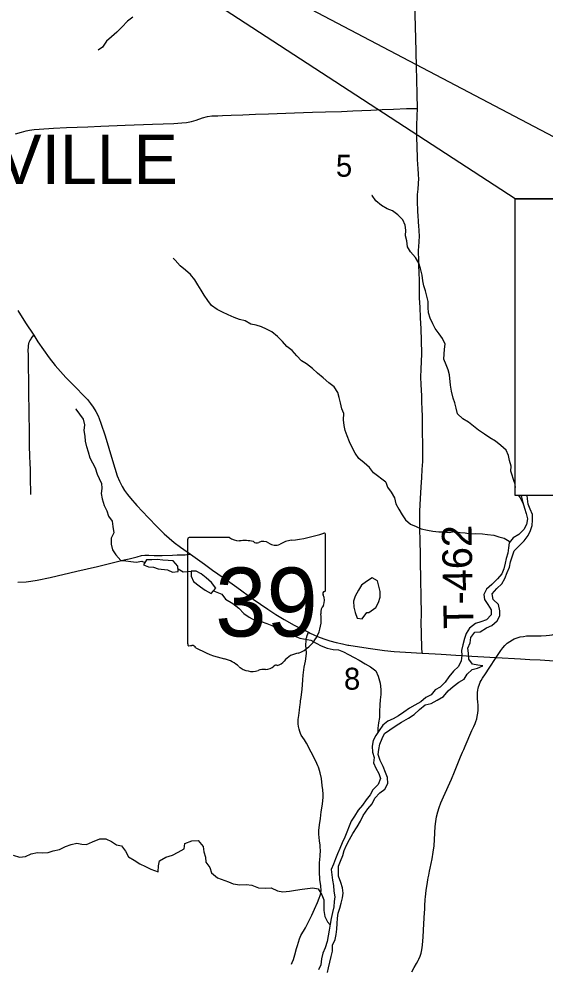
# Model space of a CAD drawing. Extents: x -7.5 to 53.5, y 0 to 22.
# Drawn here: x 5.577 to 6.583, y 15.27 to 17.086 of the extents above; entities that cross this region are included whole.
import ezdxf

# ---------------------------------------------------------------- set-up
doc = ezdxf.new("R2010")
doc.units = 0
for name, color, linetype in [('GM_X_Corporation_Text', 7, 'Continuous'), ('GM_X_Major_River', 7, 'Continuous'), ('GM_X_Minor_Lake', 7, 'Continuous'), ('GM_X_Minor_River', 7, 'Continuous'), ('GM_X_Section_Text', 7, 'Continuous'), ('GM_X_State_Location', 7, 'Continuous'), ('GM_X_State_Route', 7, 'Continuous'), ('GM_X_State_Shield', 7, 'Continuous'), ('GM_X_Township_Road', 7, 'Continuous'), ('GM_X_Township_Road_Text', 7, 'Continuous'), ('SH_Text', 7, 'Continuous')]:
    doc.layers.add(name, color=color, linetype=linetype)

msp = doc.modelspace()

# ---------------------------------------------------------------- linework, layer by layer
at = {"layer": 'GM_X_Major_River'}
for points in [[(6.5379, 16.1744), (6.5382, 16.1712), (6.5406, 16.161), (6.5437, 16.1504), (6.5472, 16.1398), (6.5496, 16.1299), (6.5478, 16.1189), (6.5429, 16.1094), (6.5332, 16.0998), (6.5226, 16.0933), (6.5148, 16.0837), (6.5137, 16.0742), (6.5119, 16.064), (6.509, 16.0541), (6.5072, 16.0446), (6.5046, 16.0343), (6.5009, 16.0248), (6.4923, 16.0149), (6.4818, 16.0038), (6.4716, 15.995), (6.466, 15.9851), (6.4672, 15.9756), (6.4741, 15.9658), (6.4803, 15.9556), (6.48, 15.9461), (6.4714, 15.9362), (6.4608, 15.9327), (6.4502, 15.9296), (6.4386, 15.9207), (6.4322, 15.9104), (6.4293, 15.9009), (6.426, 15.8884), (6.4238, 15.8777), (6.4243, 15.8683), (6.4228, 15.858), (6.418, 15.847), (6.4082, 15.8385), (6.3996, 15.8275), (6.3921, 15.8172), (6.3828, 15.8076), (6.3729, 15.8026), (6.3655, 15.793), (6.3556, 15.788), (6.3459, 15.7796), (6.3342, 15.773), (6.3244, 15.7673), (6.3135, 15.76), (6.3033, 15.7527), (6.2931, 15.7473), (6.2826, 15.7423), (6.2728, 15.735), (6.266, 15.7247), (6.2597, 15.7151), (6.2548, 15.7056), (6.2527, 15.695), (6.2532, 15.6832), (6.2563, 15.673), (6.2552, 15.6631), (6.2599, 15.6529), (6.2656, 15.6427), (6.2688, 15.6329), (6.2639, 15.6211), (6.2542, 15.6111), (6.2486, 15.6016), (6.2411, 15.5921), (6.234, 15.5821), (6.2261, 15.5726), (6.219, 15.5608), (6.2123, 15.5512), (6.209, 15.5417), (6.2045, 15.5303), (6.2004, 15.5204), (6.1956, 15.5101), (6.1908, 15.4991), (6.1867, 15.4888), (6.1826, 15.4789), (6.1789, 15.469), (6.1745, 15.4591), (6.1753, 15.4485), (6.1766, 15.4386), (6.1789, 15.4284), (6.1794, 15.4174), (6.1814, 15.4068), (6.18, 15.3973), (6.1793, 15.3871), (6.1767, 15.3768), (6.1742, 15.365), (6.1724, 15.354), (6.1702, 15.343), (6.1688, 15.332), (6.1666, 15.3213), (6.163, 15.3092), (6.1585, 15.2985), (6.156, 15.2879), (6.1545, 15.2765), (6.1501, 15.2666)], [(6.1676, 15.2614), (6.1694, 15.2709), (6.1716, 15.2815), (6.1745, 15.2926), (6.1767, 15.3024), (6.1766, 15.3138), (6.1818, 15.3249), (6.1836, 15.3347), (6.185, 15.3446), (6.186, 15.3556), (6.1863, 15.3655), (6.1874, 15.375), (6.1911, 15.3849), (6.1936, 15.3944), (6.1962, 15.4043), (6.1973, 15.4138), (6.196, 15.424), (6.1925, 15.4338), (6.1886, 15.4463), (6.1884, 15.4653), (6.1922, 15.4748), (6.1966, 15.4855), (6.1992, 15.495), (6.2036, 15.5053), (6.2096, 15.5159), (6.2159, 15.5274), (6.2238, 15.5403), (6.2301, 15.551), (6.2357, 15.5624), (6.2447, 15.5746), (6.2525, 15.5846), (6.2581, 15.5952), (6.2671, 15.6052), (6.2769, 15.6125), (6.2829, 15.6235), (6.282, 15.6345), (6.2781, 15.6444), (6.2735, 15.6557), (6.2677, 15.6674), (6.2642, 15.6788), (6.2652, 15.6886), (6.2674, 15.6985), (6.2719, 15.7092), (6.2763, 15.7187), (6.2865, 15.726), (6.2985, 15.7341), (6.3087, 15.741), (6.3223, 15.7483), (6.3332, 15.7556), (6.3434, 15.7652), (6.3543, 15.7736), (6.3656, 15.7763), (6.3769, 15.7829), (6.3894, 15.7898), (6.398, 15.8009), (6.4077, 15.8089), (6.4183, 15.817), (6.4288, 15.8232), (6.4341, 15.8327), (6.4442, 15.8415), (6.4544, 15.8439), (6.4646, 15.8485), (6.4547, 15.8499), (6.4445, 15.8514), (6.4376, 15.8615), (6.4371, 15.8725), (6.4359, 15.882), (6.4403, 15.8923), (6.4414, 15.9029), (6.4492, 15.9129), (6.4595, 15.9137), (6.4711, 15.921), (6.4813, 15.9256), (6.4915, 15.9345), (6.4967, 15.944), (6.497, 15.9535), (6.4942, 15.966), (6.4839, 15.9757), (6.4819, 15.9863), (6.4909, 15.9963), (6.5007, 16.0055), (6.5067, 16.0154), (6.5111, 16.0268), (6.5156, 16.0375), (6.5174, 16.0473), (6.521, 16.0588), (6.5244, 16.0683), (6.5338, 16.0778), (6.5435, 16.0874), (6.551, 16.0977), (6.5555, 16.1076), (6.5588, 16.1171), (6.5591, 16.1274), (6.559, 16.138), (6.5551, 16.1482), (6.5508, 16.158), (6.5496, 16.1683), (6.5491, 16.1744)]]:
    msp.add_lwpolyline(points, dxfattribs=at)
at = {"layer": 'GM_X_Minor_Lake'}
for points in [[(5.8724, 16.0492), (5.8626, 16.0502), (5.8527, 16.0505), (5.8413, 16.052), (5.8311, 16.0511), (5.8209, 16.051), (5.8153, 16.0415), (5.8248, 16.0378), (5.8343, 16.0375), (5.8438, 16.0342)], [(5.8438, 16.0342), (5.8616, 16.0324), (5.8711, 16.0276), (5.8817, 16.0288), (5.8812, 16.0394), (5.8724, 16.0492)], [(5.9352, 16.0167), (5.9257, 16.0242), (5.9162, 16.0295), (5.9067, 16.0298), (5.9064, 16.0203), (5.9114, 16.0101), (5.9221, 16.0014), (5.9244, 15.9995)], [(5.9244, 15.9995), (5.9336, 15.9932), (5.9446, 15.9868), (5.9536, 15.9968), (5.9452, 16.0081), (5.9352, 16.0167)], [(6.2631, 16.0111), (6.2528, 16.0171), (6.2419, 16.0098), (6.2321, 16.0025), (6.2265, 15.993), (6.2205, 15.9815), (6.2168, 15.972), (6.2177, 15.961), (6.22, 15.9508), (6.2243, 15.9398), (6.2338, 15.9384), (6.2424, 15.9506), (6.2466, 15.9502)], [(6.2466, 15.9502), (6.2597, 15.9602), (6.2646, 15.9697), (6.2683, 15.98), (6.2678, 15.9906), (6.2654, 16.0012), (6.2631, 16.0111)]]:
    msp.add_lwpolyline(points, dxfattribs=at)
at = {"layer": 'GM_X_Minor_River'}
for points in [[(5.7948, 17.0893), (5.7846, 17.0818), (5.7742, 17.0705), (5.7647, 17.0607), (5.7544, 17.0521), (5.7448, 17.0435), (5.7368, 17.0322), (5.7291, 17.0262)], [(6.5251, 16.1992), (6.5181, 16.2208), (6.5185, 16.2306), (6.5156, 16.2416), (6.5134, 16.2511), (6.5089, 16.261), (6.4987, 16.2698), (6.4886, 16.2783), (6.4776, 16.2848), (6.4675, 16.2917), (6.4562, 16.2991), (6.4366, 16.3144), (6.4264, 16.3209), (6.4159, 16.3305), (6.4133, 16.3415), (6.4111, 16.3514), (6.4078, 16.3609), (6.4041, 16.3739), (6.4027, 16.3852), (6.4006, 16.405), (6.398, 16.4149), (6.3939, 16.4244), (6.3898, 16.435), (6.3903, 16.4445), (6.3911, 16.4544), (6.3923, 16.4642), (6.3875, 16.4745), (6.3807, 16.484), (6.3729, 16.4936), (6.3688, 16.5031), (6.3636, 16.5138), (6.3602, 16.5237), (6.3596, 16.5339), (6.3596, 16.5453), (6.3571, 16.5555), (6.3549, 16.5658), (6.3516, 16.5753), (6.3497, 16.5852), (6.3483, 16.5962), (6.3454, 16.6084), (6.3421, 16.619), (6.3353, 16.6297), (6.3259, 16.6404), (6.3203, 16.6503), (6.3189, 16.6617), (6.3163, 16.6712), (6.3172, 16.6822), (6.3161, 16.6917), (6.3113, 16.7016), (6.3019, 16.7111), (6.2913, 16.7192), (6.2811, 16.7227), (6.2706, 16.7293), (6.26, 16.7381), (6.2529, 16.7484), (6.2518, 16.7484)], [(6.2791, 16.2002), (6.255, 16.2175), (6.2475, 16.2281), (6.2373, 16.2366), (6.2275, 16.245), (6.2204, 16.2553), (6.2144, 16.266), (6.2096, 16.277), (6.2048, 16.2884), (6.2011, 16.2987), (6.1993, 16.3082), (6.1982, 16.3192), (6.1983, 16.331), (6.195, 16.3405), (6.1924, 16.3519), (6.1898, 16.3618), (6.1869, 16.3713), (6.1802, 16.382), (6.17, 16.39), (6.1591, 16.3992), (6.1485, 16.4084), (6.1384, 16.4172), (6.1271, 16.4261), (6.1173, 16.4318), (6.1086, 16.4414), (6.1, 16.4517), (6.0898, 16.4594), (6.0812, 16.4689), (6.0714, 16.4789), (6.0609, 16.4877), (6.0507, 16.4927), (6.0409, 16.4974), (6.0307, 16.5001), (6.0208, 16.5021), (6.0099, 16.5083), (5.9989, 16.511), (5.9891, 16.5149), (5.9774, 16.5203), (5.9668, 16.5253), (5.9566, 16.5304), (5.9457, 16.5381), (5.9386, 16.5476), (5.9314, 16.5579), (5.9258, 16.5674), (5.9195, 16.5773), (5.9135, 16.5873), (5.9056, 16.5972), (5.8958, 16.6052), (5.8853, 16.6141), (5.8763, 16.6244), (5.8721, 16.6286)], [(5.735, 16.1979), (5.7273, 16.2143), (5.7237, 16.2265), (5.7188, 16.236), (5.7136, 16.2459), (5.7106, 16.2573), (5.7069, 16.2672), (5.7044, 16.2782), (5.7037, 16.2881), (5.7023, 16.2987), (5.7035, 16.3097), (5.7009, 16.3207), (5.6867, 16.3398), (5.6863, 16.3402)], [(5.735, 16.1979), (5.7355, 16.188), (5.7348, 16.1782), (5.7365, 16.1683), (5.7404, 16.1551), (5.7454, 16.1453), (5.7485, 16.135), (5.7554, 16.1252), (5.757, 16.115), (5.7586, 16.1029), (5.7538, 16.093), (5.7539, 16.0812), (5.7563, 16.0706), (5.7624, 16.0608), (5.772, 16.0503), (5.7815, 16.0492), (5.7914, 16.0478), (5.8016, 16.0467), (5.8126, 16.0487), (5.8179, 16.046)], [(6.2791, 16.2002), (6.2819, 16.1903), (6.2892, 16.1805), (6.2957, 16.1696), (6.2981, 16.1582), (6.3039, 16.148), (6.31, 16.1374), (6.3166, 16.1276), (6.3261, 16.1197), (6.3368, 16.1153), (6.3467, 16.1108), (6.3588, 16.1082), (6.3687, 16.1064), (6.38, 16.105), (6.3895, 16.1051), (6.3998, 16.1033), (6.4096, 16.1053), (6.421, 16.1034), (6.4305, 16.1028), (6.4403, 16.1013), (6.4509, 16.1018), (6.4634, 16.1011), (6.4733, 16.0997), (6.4854, 16.0983), (6.4949, 16.0953), (6.5052, 16.0928), (6.5147, 16.0868), (6.5162, 16.0855)], [(6.5251, 16.1992), (6.5259, 16.1897), (6.5259, 16.1896)], [(6.5323, 16.1744), (6.5356, 16.17), (6.5409, 16.1596)], [(5.8815, 16.034), (5.8916, 16.0285), (5.9067, 16.0298)], [(5.9494, 15.9921), (5.9655, 15.9859), (5.9724, 15.976), (5.9861, 15.9678), (5.9975, 15.9588), (6.0071, 15.9486), (6.0174, 15.9415), (6.0288, 15.9352), (6.0406, 15.933), (6.0512, 15.9297), (6.0611, 15.9256), (6.0718, 15.9207), (6.0836, 15.9166), (6.0935, 15.9095), (6.1049, 15.9054), (6.1144, 15.9017), (6.1356, 15.8974), (6.1455, 15.8917), (6.1554, 15.8865), (6.1665, 15.8821), (6.1782, 15.8799), (6.1881, 15.8792), (6.198, 15.8755), (6.2075, 15.8699), (6.2185, 15.8647), (6.2281, 15.8594), (6.2395, 15.8523), (6.2498, 15.8467), (6.2597, 15.8392), (6.2643, 15.829), (6.2682, 15.8154), (6.2691, 15.8032), (6.2696, 15.7938), (6.2682, 15.7835), (6.2671, 15.7736), (6.2668, 15.7611), (6.2666, 15.7497), (6.2648, 15.7395), (6.2633, 15.7292), (6.2634, 15.7207)], [(5.5665, 15.4863), (5.5782, 15.4822), (5.5896, 15.4838), (5.6009, 15.4889), (5.6126, 15.4912), (5.6233, 15.4909), (5.6331, 15.4914), (5.6429, 15.4945), (5.6546, 15.4973), (5.6663, 15.5031), (5.6769, 15.5069), (5.6879, 15.5089), (5.6974, 15.5071), (5.7068, 15.5068), (5.7178, 15.5118), (5.7318, 15.5173), (5.7435, 15.5177), (5.7545, 15.5125), (5.7641, 15.5062), (5.7736, 15.5043), (5.7809, 15.4938), (5.787, 15.4828), (5.7977, 15.4768), (5.8087, 15.4697), (5.8194, 15.4645), (5.8293, 15.4593), (5.8434, 15.4541), (5.8444, 15.4655), (5.8462, 15.4754), (5.8579, 15.4823), (5.8707, 15.4862), (5.8817, 15.492), (5.8933, 15.4985), (5.8948, 15.5084), (5.9076, 15.5134), (5.9201, 15.5143), (5.9293, 15.5026), (5.9309, 15.4927), (5.934, 15.4822), (5.9349, 15.4727), (5.9426, 15.4625), (5.9457, 15.4527), (5.9571, 15.4429), (5.9777, 15.4355), (5.9872, 15.4314), (5.9997, 15.4292), (6.0118, 15.4304), (6.0228, 15.429), (6.0354, 15.4238), (6.0479, 15.4228)], [(6.0479, 15.4228), (6.0596, 15.4236), (6.0714, 15.4177), (6.082, 15.4162), (6.0945, 15.4175), (6.1063, 15.4195), (6.1187, 15.4211), (6.129, 15.4223), (6.1392, 15.4239), (6.1494, 15.4221), (6.1567, 15.4104), (6.1606, 15.4006), (6.1603, 15.3907), (6.16, 15.3801), (6.1624, 15.3691), (6.1674, 15.3589), (6.1721, 15.3526)]]:
    msp.add_lwpolyline(points, dxfattribs=at)
at = {"layer": 'GM_X_State_Route'}
for points in [[(5.575, 16.5284), (5.59, 16.5048), (5.6055, 16.4809)], [(5.6055, 16.4809), (5.6137, 16.4684), (5.6241, 16.453), (5.6351, 16.4379), (5.6466, 16.4233), (5.6567, 16.4114), (5.6672, 16.4), (5.6846, 16.3823), (5.702, 16.3647), (5.7083, 16.3578), (5.7141, 16.3506), (5.7194, 16.3431), (5.7242, 16.3352), (5.7285, 16.327), (5.731, 16.3214), (5.7342, 16.3127), (5.7423, 16.2886), (5.7561, 16.2414), (5.7605, 16.2267), (5.7654, 16.2121), (5.7695, 16.2021), (5.7748, 16.1915), (5.7792, 16.1838), (5.7847, 16.1761), (5.7907, 16.169), (5.803, 16.1552), (5.8243, 16.132), (5.8413, 16.1142), (5.8552, 16.101), (5.8644, 16.0926), (5.874, 16.0847), (5.8864, 16.0753), (5.9052, 16.0619)], [(5.9052, 16.0619), (5.9318, 16.043), (5.9477, 16.0317), (5.9679, 16.0174), (5.9807, 16.0083), (5.9939, 15.9988), (6.0252, 15.9762), (6.0532, 15.9567), (6.0688, 15.9465), (6.0847, 15.9369), (6.1037, 15.9263), (6.1175, 15.9192), (6.1309, 15.9126)], [(6.1309, 15.9126), (6.1343, 15.911), (6.1482, 15.9048), (6.1602, 15.9003), (6.172, 15.8964), (6.184, 15.893), (6.1962, 15.8903), (6.2065, 15.8883)], [(6.2065, 15.8883), (6.2084, 15.888), (6.2453, 15.8824), (6.2761, 15.8781), (6.2947, 15.8761), (6.3164, 15.8745), (6.3481, 15.8725)], [(6.3481, 15.8725), (6.3496, 15.8724), (6.3846, 15.8706), (6.4125, 15.8689), (6.4435, 15.867), (6.4776, 15.865), (6.4899, 15.8644)], [(6.4899, 15.8644), (6.5363, 15.8619), (6.5545, 15.8608)], [(6.5545, 15.8608), (6.5737, 15.8597), (6.6009, 15.8583)]]:
    msp.add_lwpolyline(points, dxfattribs=at)
at = {"layer": 'GM_X_State_Shield'}
for p, q in [((5.8999, 16.0906), (5.8999, 15.8905)), ((5.9798, 16.094), (5.9025, 16.094)), ((6.1636, 15.9943), (6.1636, 16.099)), ((6.1636, 15.9943), (6.1636, 15.9943))]:
    msp.add_line(p, q, dxfattribs=at)
for centre, radius, start, end in [((5.903, 16.091), 0.00305, 98.1301, 188.1301), ((5.9981, 16.1173), 0.0296, 231.6195, 271.1119), ((6.1054, 16.0329), 0.0563, 97.3462, 120.7689), ((6.0697, 16.3669), 0.2796, 275.8445, 288.9065), ((6.1607, 16.0994), 0.00294, 351.8621, 97.738), ((6.008, 15.9817), 0.1064, 80.4867, 94.9883), ((6.0321, 16.0921), 0.00855, 219.7921, 297.1024), ((6.0447, 16.0689), 0.0178, 54.4667, 119.1411), ((6.0676, 16.1007), 0.0214, 233.8562, 294.8282), ((6.1629, 15.9866), 0.00454, 107.944, 210.337), ((6.134, 15.9734), 0.0273, 340.033, 23.6496), ((6.1605, 15.9939), 0.00314, 289.6038, 7.7341), ((6.1741, 15.9505), 0.0198, 136.8065, 186.9296), ((6.0854, 15.9372), 0.0699, 292.3089, 8.9858), ((5.903, 15.89), 0.00308, 171.9584, 258.3066), ((5.9035, 15.9105), 0.0235, 267.339, 280.6039), ((5.9083, 15.8789), 0.00848, 29.7484, 93.2717), ((6.0153, 16.0587), 0.2019, 240.4129, 257.1985), ((6.1148, 15.8343), 0.0383, 94.4031, 142.5768), ((5.9551, 15.8006), 0.0632, 47.1842, 75.836), ((6.0663, 15.8711), 0.0226, 282.8732, 323.2771), ((6.0235, 15.8779), 0.0401, 230.7004, 286.2918), ((6.0466, 15.8087), 0.0329, 85.6951, 111.2099), ((6.0496, 15.8629), 0.0214, 268.777, 315.5493), ((6.0689, 15.8436), 0.00601, 65.7517, 132.6484)]:
    msp.add_arc(centre, radius, start, end, dxfattribs=at)
at = {"layer": 'GM_X_Township_Road'}
for points in [[(6.3391, 16.915), (6.3391, 16.916), (6.3388, 16.9408), (6.338, 16.9719), (6.3375, 16.9936), (6.337, 17.0246), (6.3345, 17.1183)], [(5.5705, 16.8662), (5.5824, 16.8695), (5.5913, 16.872), (5.5974, 16.8734), (5.6065, 16.8748), (5.6158, 16.8756), (5.6437, 16.877), (5.6685, 16.8782), (5.7088, 16.88), (5.7336, 16.8812), (5.7802, 16.883), (5.8329, 16.8847), (5.8733, 16.8862), (5.8888, 16.8873), (5.898, 16.8883), (5.9072, 16.8898), (5.9162, 16.8923), (5.9282, 16.8969), (5.9379, 16.8995), (5.9464, 16.9006), (5.9575, 16.901), (5.9664, 16.9013), (5.9834, 16.9019), (6.0051, 16.9027), (6.0299, 16.9038), (6.0547, 16.9048), (6.1043, 16.9065), (6.1384, 16.9076), (6.1632, 16.9085), (6.1942, 16.9094), (6.2159, 16.9101), (6.25, 16.9117), (6.2717, 16.9127), (6.2934, 16.9137), (6.3181, 16.9147), (6.3305, 16.9149), (6.3391, 16.915)], [(6.3401, 16.7174), (6.3398, 16.7214), (6.3393, 16.7341), (6.3391, 16.7438), (6.3395, 16.7505), (6.3407, 16.7603), (6.3415, 16.7713), (6.3418, 16.7809), (6.3415, 16.7871), (6.3412, 16.79), (6.3406, 16.7997), (6.3393, 16.817), (6.3392, 16.8201), (6.3391, 16.8263), (6.3387, 16.8355), (6.3385, 16.8447), (6.3384, 16.857), (6.3383, 16.8694), (6.3383, 16.8818), (6.3388, 16.9005), (6.3391, 16.915)], [(6.3468, 15.9413), (6.3468, 15.952), (6.3463, 15.9768), (6.3455, 16.0172), (6.3452, 16.0451), (6.3449, 16.0606), (6.3445, 16.0885), (6.344, 16.1102), (6.3439, 16.1226), (6.3438, 16.1288), (6.3436, 16.1349), (6.3438, 16.1442), (6.3451, 16.1688), (6.3465, 16.1902), (6.3476, 16.2085), (6.3485, 16.2239), (6.3494, 16.2393), (6.3498, 16.2546), (6.3497, 16.2701), (6.3494, 16.2794), (6.3492, 16.2887), (6.3491, 16.2979), (6.3489, 16.3103), (6.3487, 16.3195), (6.3487, 16.3257), (6.3483, 16.3402), (6.348, 16.353), (6.3474, 16.3654), (6.347, 16.3752), (6.3462, 16.3876), (6.3458, 16.3999), (6.3462, 16.4165), (6.3472, 16.4303), (6.3478, 16.4459), (6.3472, 16.4712), (6.3462, 16.4933), (6.3454, 16.514), (6.3446, 16.5345), (6.3435, 16.5519), (6.3434, 16.5678), (6.3433, 16.5857), (6.3427, 16.6012), (6.3419, 16.6142), (6.3417, 16.6279), (6.3415, 16.6378), (6.3415, 16.644), (6.3419, 16.6504), (6.3426, 16.6605), (6.343, 16.6704), (6.3425, 16.6808), (6.3418, 16.6908), (6.3413, 16.6968), (6.341, 16.7018), (6.3406, 16.707), (6.3405, 16.7104), (6.3401, 16.7174)], [(5.6001, 16.176), (5.6002, 16.1822), (5.5996, 16.2039), (5.5994, 16.2132), (5.5992, 16.2225), (5.5992, 16.2257), (5.5989, 16.235), (5.5984, 16.2504), (5.598, 16.2565), (5.5977, 16.2626), (5.5975, 16.275), (5.5973, 16.2999), (5.597, 16.3279), (5.5963, 16.3776), (5.5962, 16.3963), (5.5959, 16.418), (5.5957, 16.4242), (5.5955, 16.4335), (5.5953, 16.4429), (5.5951, 16.4522), (5.5953, 16.4584), (5.5956, 16.4615), (5.5962, 16.4645), (5.5971, 16.4675), (5.5983, 16.4704), (5.5998, 16.4731), (5.601, 16.4749), (5.6032, 16.4778), (5.6055, 16.4809)], [(5.5755, 16.0086), (5.5909, 16.0095), (5.6002, 16.0104), (5.6124, 16.0123), (5.6368, 16.0173), (5.6882, 16.0294), (5.7275, 16.0386), (5.7607, 16.0466), (5.7787, 16.0511), (5.7878, 16.0531), (5.8033, 16.0571), (5.8115, 16.0593), (5.818, 16.0599), (5.8254, 16.0599), (5.8357, 16.0598), (5.8514, 16.0597), (5.8708, 16.0602), (5.88, 16.0606), (5.8892, 16.0608), (5.8952, 16.061), (5.8982, 16.0613), (5.9052, 16.0619)], [(6.3481, 15.8725), (6.3477, 15.8837), (6.3476, 15.8868), (6.3468, 15.9054), (6.3467, 15.9364), (6.3468, 15.9413)], [(6.0987, 15.2779), (6.1, 15.2808), (6.1023, 15.2865), (6.105, 15.2954), (6.108, 15.3075), (6.1097, 15.3134), (6.1116, 15.3199), (6.1139, 15.3263), (6.1166, 15.3327), (6.125, 15.3472), (6.1317, 15.36), (6.1374, 15.3716), (6.1425, 15.3828), (6.1482, 15.3959), (6.1513, 15.404), (6.1532, 15.4093), (6.1545, 15.4133), (6.155, 15.4183), (6.1545, 15.4273), (6.1528, 15.4394), (6.1518, 15.454), (6.1517, 15.465), (6.1521, 15.4714), (6.1536, 15.4846), (6.1538, 15.4962), (6.1536, 15.5002), (6.1533, 15.5026), (6.153, 15.5052), (6.1517, 15.5135), (6.1505, 15.5265), (6.1506, 15.5302), (6.1506, 15.5332), (6.1519, 15.5445), (6.1538, 15.5563), (6.1555, 15.569), (6.1575, 15.5841), (6.1588, 15.5973), (6.1588, 15.6), (6.1589, 15.6031), (6.1585, 15.6109), (6.1573, 15.6198), (6.1556, 15.6332), (6.1534, 15.6438), (6.1507, 15.6527), (6.1499, 15.6548), (6.1491, 15.6569), (6.145, 15.6663), (6.1273, 15.7004), (6.1252, 15.7039), (6.1234, 15.7069), (6.1172, 15.716), (6.1157, 15.7188), (6.1141, 15.7228), (6.1129, 15.7272), (6.112, 15.7324), (6.1114, 15.7378), (6.1114, 15.7456), (6.1123, 15.7535), (6.1137, 15.7638), (6.1146, 15.7699), (6.1149, 15.7739), (6.1154, 15.7789), (6.1158, 15.7818), (6.1162, 15.7848), (6.1167, 15.7878), (6.1175, 15.7938), (6.1186, 15.803), (6.1202, 15.8214), (6.121, 15.8306), (6.1227, 15.8457), (6.125, 15.8576), (6.1266, 15.8668), (6.1269, 15.873), (6.1261, 15.8885), (6.1263, 15.8962), (6.1268, 15.9007), (6.1276, 15.9036), (6.1287, 15.9065), (6.1309, 15.9126)], [(6.4899, 15.8644), (6.4935, 15.87), (6.4986, 15.8778), (6.5023, 15.8828), (6.5065, 15.8874), (6.511, 15.8916), (6.516, 15.8953), (6.5213, 15.8985), (6.5241, 15.8999), (6.5298, 15.9022), (6.5358, 15.9038), (6.5419, 15.9049), (6.5481, 15.9057), (6.5574, 15.906), (6.5761, 15.9061), (6.5854, 15.9064), (6.5916, 15.9069), (6.5966, 15.9077), (6.6007, 15.9089), (6.6065, 15.911), (6.6121, 15.9137), (6.6148, 15.9152), (6.6156, 15.9157)], [(6.451, 15.7421), (6.4526, 15.7473), (6.4538, 15.7517), (6.4548, 15.7578), (6.4553, 15.7639), (6.4554, 15.7701), (6.4552, 15.7732), (6.4546, 15.7793), (6.4542, 15.7854), (6.4541, 15.7913), (6.4544, 15.797), (6.455, 15.8026), (6.4555, 15.8054), (6.4563, 15.8083), (6.4572, 15.8112), (6.4595, 15.8171), (6.4612, 15.8205), (6.4639, 15.8247), (6.4693, 15.8331), (6.4764, 15.8443), (6.4899, 15.8644)], [(6.3285, 15.2633), (6.3328, 15.2713), (6.3376, 15.2792), (6.3408, 15.2846), (6.3422, 15.2873), (6.3447, 15.293), (6.3466, 15.2989), (6.348, 15.305), (6.3491, 15.3142), (6.3502, 15.3297), (6.3516, 15.3546), (6.3529, 15.3762), (6.3532, 15.3823), (6.3535, 15.3884), (6.354, 15.4018), (6.3546, 15.4061), (6.3562, 15.4194), (6.3579, 15.4301), (6.3594, 15.4391), (6.3599, 15.4426), (6.3608, 15.4477), (6.3622, 15.4553), (6.3636, 15.4613), (6.3672, 15.4795), (6.3694, 15.4917), (6.371, 15.504), (6.3721, 15.5164), (6.3732, 15.5413), (6.3742, 15.5505), (6.3758, 15.5597), (6.378, 15.5688), (6.3807, 15.5777), (6.384, 15.5864), (6.389, 15.5977), (6.4041, 15.6315), (6.4102, 15.6457), (6.4217, 15.6745), (6.4253, 15.6831), (6.4278, 15.6887), (6.4305, 15.6948), (6.4432, 15.7247), (6.447, 15.7327), (6.4495, 15.7383), (6.451, 15.7421)]]:
    msp.add_lwpolyline(points, dxfattribs=at)
at = {"layer": 'SH_Text'}
for points in [[(6.8259, 16.7419), (6.5259, 16.7419), (5.2686, 17.561)], [(6.5259, 16.7419), (8.061, 16.7419), (8.061, 16.1744), (6.5259, 16.1744)]]:
    msp.add_lwpolyline(points, close=True, dxfattribs=at)

# ---------------------------------------------------------------- texts
at = {"layer": 'GM_X_Corporation_Text'}
msp.add_text('LOUDONVILLE', height=0.094697, rotation=0, dxfattribs=at).set_placement((4.9943, 16.7702))
at = {"layer": 'GM_X_Section_Text'}
for s, p in [('5', (6.1834, 16.7843)), ('8', (6.1988, 15.8029))]:
    msp.add_text(s, height=0.0419, rotation=0, dxfattribs=at).set_placement(p)
at = {"layer": 'GM_X_State_Location'}
msp.add_text('39', height=0.000189, rotation=0, dxfattribs=at).set_placement((5.9811, 15.9634))
for s in ['s', 'r']:
    msp.add_text(s, height=0.000189, dxfattribs=at).set_placement((6.0288, 15.9772))
at = {"layer": 'GM_X_State_Shield'}
msp.add_text('39', height=0.13184, dxfattribs=at).set_placement((5.9526, 15.9046))
at = {"layer": 'GM_X_Township_Road_Text'}
msp.add_text('T-462', height=0.05682, rotation=91.1242, dxfattribs=at).set_placement((6.4464, 15.9199))

doc.saveas('drawing.dxf')
